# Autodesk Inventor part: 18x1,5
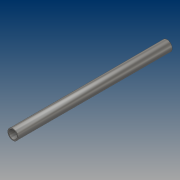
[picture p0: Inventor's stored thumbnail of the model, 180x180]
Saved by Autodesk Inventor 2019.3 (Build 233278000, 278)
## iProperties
Created: 2019-01
Part Number: 18x1,5
Material: Ocel, měkká
Document SubType Name: Modeling
Designer: B-hon
Density: 7.85 g/cm^3
Appearance: Pololeštěná
Author: B-hon
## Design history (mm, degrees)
sketch "Náčrt1"
  geometry: C1 r 9 at (0, 0); C2 r 7.5 at (0, 0); 1 further point
  constraints: 2 centre point, 1 coincident
  dimensions: "d0" = 18 diameter of C1; "d1" = 1.5 radial gap between concentric circles of C1 C2
extrude "Vysunutí1" new body sketch "Náčrt1" distance "d2" = 267.25; taper "d3" = 0 deg
node "Těleso1"
